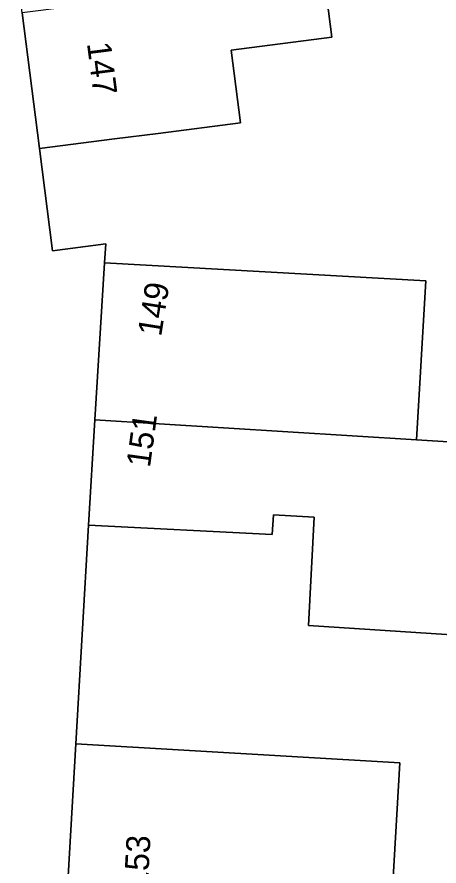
# Model space of a CAD drawing. Extents: x 162879 to 165540, y 384011 to 385181.
# Drawn here: x 164091.41 to 164109.04, y 384371.44 to 384406.9 of the extents above; entities that cross this region are included whole.
import ezdxf

# ---------------------------------------------------------------- set-up
doc = ezdxf.new("R2010")
doc.units = 0
for name, color, linetype in [('IMGEO_Erf', 7, 'Continuous'), ('IMGEO_Pand', 7, 'Continuous'), ('IMGEO_Pand_nummerreeks', 7, 'Continuous'), ('IMGEO_Voetpad_open', 7, 'Continuous')]:
    doc.layers.add(name, color=color, linetype=linetype)

msp = doc.modelspace()

# ---------------------------------------------------------------- linework, layer by layer
at = {"layer": 'IMGEO_Erf'}
for points in [[(164104.225, 384408.684), (164104.56, 384406.054), (164100.354, 384405.517), (164100.742, 384402.48), (164097.31, 384402.042), (164095.489, 384401.81), (164092.35, 384401.409), (164092.895, 384397.137), (164095.127, 384397.422), (164095.062, 384396.637), (164108.486, 384395.877), (164108.105, 384389.235), (164113.032, 384388.928)], [(164112.561, 384380.903), (164103.582, 384381.486), (164103.827, 384386.009), (164102.12, 384386.102), (164102.075, 384385.283), (164094.394, 384385.679), (164093.863, 384376.535), (164107.409, 384375.743), (164107.101, 384370.472)]]:
    msp.add_lwpolyline(points, dxfattribs=at)
at = {"layer": 'IMGEO_Pand'}
for points in [[(164091.626, 384407.078), (164092.35, 384401.409), (164095.489, 384401.81), (164097.31, 384402.042), (164100.742, 384402.48), (164100.354, 384405.517), (164104.56, 384406.054), (164104.225, 384408.684)], [(164094.662, 384390.073), (164108.105, 384389.235), (164108.486, 384395.877), (164095.062, 384396.637)], [(164094.662, 384390.073), (164094.394, 384385.679), (164102.075, 384385.283), (164102.12, 384386.102), (164103.827, 384386.009), (164103.582, 384381.486), (164112.561, 384380.903), (164112.464, 384379.056), (164115.557, 384378.894), (164115.762, 384382.577), (164112.667, 384382.749), (164113.032, 384388.928), (164108.105, 384389.235)], [(164107.409, 384375.743), (164093.863, 384376.535), (164093.334, 384367.41), (164096.843, 384367.207), (164100.352, 384367.003), (164100.384, 384367.602), (164107.101, 384370.472)]]:
    msp.add_lwpolyline(points, close=True, dxfattribs=at)
at = {"layer": 'IMGEO_Voetpad_open'}
msp.add_lwpolyline([(164092.471, 384358.045), (164098.816, 384360.506), (164098.233, 384361.24), (164096.843, 384367.207), (164093.334, 384367.41), (164093.863, 384376.535), (164094.394, 384385.679), (164094.662, 384390.073), (164095.062, 384396.637), (164095.127, 384397.422), (164092.895, 384397.137), (164092.35, 384401.409), (164091.626, 384407.078), (164090.922, 384412.599), (164090.217, 384418.12), (164089.493, 384423.793), (164088.544, 384429.83), (164086.771, 384436.397), (164086.127, 384438.809), (164083.416, 384448.962)], dxfattribs=at)

# ---------------------------------------------------------------- texts
at = {"layer": 'IMGEO_Pand_nummerreeks'}
for s, rotation, p in [('147', 277.2737, (164094.33, 384405.802)), ('149', 81.0312, (164097.431, 384393.529)), ('151', 82.1982, (164096.963, 384388.054)), ('153', 86.7916, (164096.868, 384370.47))]:
    msp.add_text(s, height=1, rotation=rotation, dxfattribs=at).set_placement(p)

doc.saveas('drawing.dxf')
